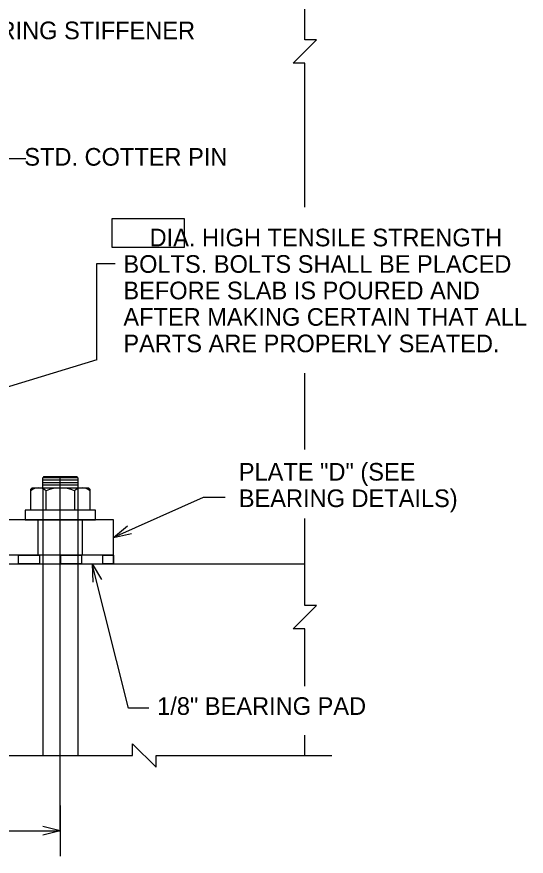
# Model space of a CAD drawing. Extents: x -2.6 to 35, y 2.5 to 26.9.
# Drawn here: x 16.34 to 19.95, y 16.09 to 22.04 of the extents above; entities that cross this region are included whole.
import ezdxf

# ---------------------------------------------------------------- set-up
doc = ezdxf.new("R2010")
doc.units = 0
doc.layers.add('Level 3', color=7, linetype='Continuous')

msp = doc.modelspace()

# ---------------------------------------------------------------- linework, layer by layer
at = {"layer": 'Level 3'}
for p, q in [((16.3998, 21.0308), (16.1655, 21.0308)), ((16.9035, 19.6085), (16.1949, 19.393)), ((16.5282, 18.782), (16.5192, 18.773)), ((16.5192, 18.7028), (16.5192, 18.773)), ((16.7692, 18.773), (16.5192, 18.773)), ((16.7692, 18.755), (16.5192, 18.755)), ((16.7692, 18.737), (16.5192, 18.737)), ((16.5282, 18.782), (16.7602, 18.782)), ((16.6442, 16.272), (16.6442, 18.782)), ((16.7692, 18.773), (16.7602, 18.782)), ((16.7692, 18.773), (16.7692, 18.7028)), ((16.444, 18.7008), (16.435, 18.6918)), ((16.435, 18.544), (16.435, 18.6918)), ((16.444, 18.7008), (16.8445, 18.7008)), ((16.7692, 18.719), (16.5192, 18.719)), ((16.5192, 18.7008), (16.5192, 18.4753)), ((16.543, 18.544), (16.543, 18.6799)), ((16.7455, 18.6799), (16.7455, 18.544)), ((16.7692, 18.7008), (16.7692, 18.4753)), ((16.8445, 18.7008), (16.8535, 18.6918)), ((16.8535, 18.6918), (16.8535, 18.544)), ((17.6575, 18.6327), (17.0217, 18.3503)), ((17.8128, 18.6327), (17.6575, 18.6327)), ((17.0217, 18.4753), (11.7924, 18.4753)), ((16.4879, 18.2253), (16.4879, 18.4753)), ((16.5192, 18.4753), (16.5192, 16.805)), ((16.7692, 18.4753), (16.7692, 16.805)), ((16.8005, 18.2253), (16.8005, 18.4753)), ((17.0217, 18.1626), (17.0217, 18.4753)), ((17.0217, 18.3503), (17.1203, 18.4332)), ((17.0217, 18.3503), (17.1477, 18.377)), ((17.0217, 18.2253), (11.7924, 18.2253)), ((17.0217, 18.2253), (17.0217, 18.1626)), ((9.9734, 18.1626), (18.3775, 18.1626)), ((17.1277, 17.1413), (16.8704, 18.1626)), ((16.8704, 18.1626), (16.9349, 18.051)), ((16.8704, 18.1626), (16.8748, 18.0338)), ((17.2711, 17.1413), (17.1277, 17.1413)), ((16.6442, 16.4519), (16.6442, 16.272)), ((16.6442, 16.272), (16.5192, 16.3032)), ((12.1684, 16.272), (16.6442, 16.272)), ((16.6442, 16.272), (16.5192, 16.2407)), ((16.6442, 16.272), (16.6442, 16.092))]:
    msp.add_line(p, q, dxfattribs=at)
for points in [[(18.3775, 20.6903), (18.3775, 21.709), (18.2942, 21.709), (18.4609, 21.8757), (18.3775, 21.8757), (18.3775, 22.5464)], [(16.9035, 19.6085), (16.9035, 20.2897), (17.0318, 20.2897)], [(18.3775, 18.9733), (18.3775, 19.5132)], [(18.3775, 17.2966), (18.3775, 17.7018), (18.2942, 17.7018), (18.4609, 17.8685), (18.3775, 17.8685), (18.3775, 18.4833)], [(18.3775, 16.805), (18.3775, 16.9501)], [(16.2448, 16.805), (17.1557, 16.805), (17.1557, 16.8884), (17.3224, 16.7217), (17.3224, 16.805), (18.5686, 16.805)]]:
    msp.add_lwpolyline(points, dxfattribs=at)
for points in [[(17.5245, 20.4057), (17.5245, 20.6059), (17.0092, 20.6059), (17.0092, 20.4057)], [(16.8928, 18.544), (16.3956, 18.544), (16.3956, 18.4753), (16.8928, 18.4753)], [(16.3477, 18.2253), (16.4958, 18.2253), (16.4958, 18.1626), (16.3477, 18.1626)], [(16.6472, 18.2253), (16.7953, 18.2253), (16.7953, 18.1626), (16.6472, 18.1626)], [(16.9444, 18.2253), (17.0217, 18.2253), (17.0217, 18.1626), (16.9444, 18.1626)]]:
    msp.add_lwpolyline(points, close=True, dxfattribs=at)
for centre, radius, start, end in [((16.489, 18.6206), 0.0802, 47.64442, 132.35558), ((16.6442, 18.4453), 0.2555, 66.65071, 113.34929), ((16.7995, 18.6206), 0.0802, 47.64442, 132.35558)]:
    msp.add_arc(centre, radius, start, end, dxfattribs=at)

# ---------------------------------------------------------------- texts
for s, p in [('BEARING STIFFENER', (15.8717, 21.8788)), (' STD. COTTER PIN', (16.3424, 20.9833)), ('    DIA. HIGH TENSILE STRENGTH', (17.0911, 20.4117)), ('BOLTS. BOLTS SHALL BE PLACED', (17.0911, 20.2242)), ('BEFORE SLAB IS POURED AND', (17.0911, 20.0367)), ('AFTER MAKING CERTAIN THAT ALL', (17.0911, 19.8492)), ('PARTS ARE PROPERLY SEATED.', (17.0911, 19.6617)), ('PLATE "D" (SEE ', (17.9091, 18.7524)), ('BEARING DETAILS)', (17.9091, 18.5649)), ('1/8" BEARING PAD', (17.3306, 17.093))]:
    msp.add_text(s, height=0.125, dxfattribs=at).set_placement(p)

doc.saveas('drawing.dxf')
